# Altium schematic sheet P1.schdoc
size 297 x 210 mm; Symbol: Sheet-Symbol_A4; Company: 嘉立创EDA; Version: V1.0; Page Size: A4; @Project Name: 四轴飞行器; @Page Count: 1; @Update Date: 2025-12-14; @Create Date: 2025-11-12; @Schematic Name: Schematic1; @Page No: 1; @Page Name: P1; Device: Sheet-Symbol_A4; @Board Name: 飞行器; @Create Time: 09:09:34; @Update Time: 14:06:36
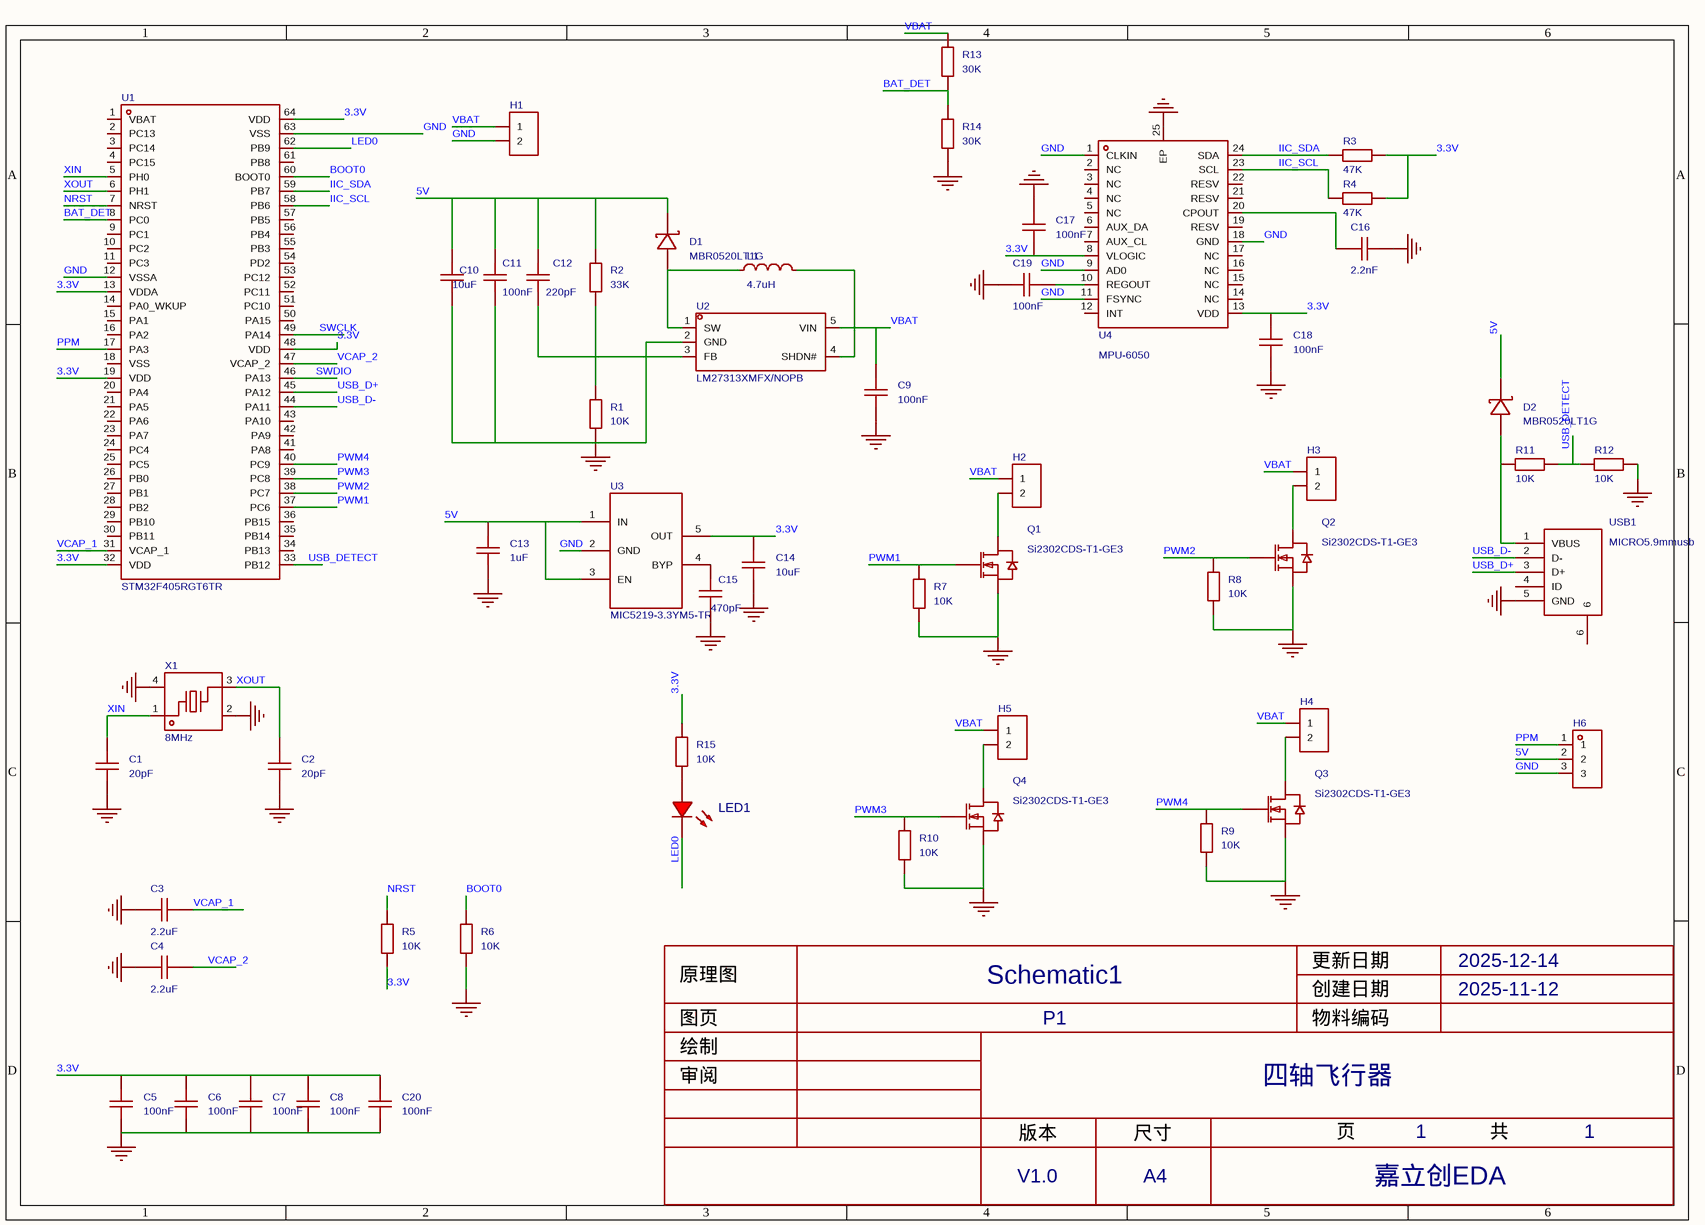
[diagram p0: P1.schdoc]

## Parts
C1  20pF  [C0603]
C2  20pF  [C0603]
C3  2.2uF  [C0603]
C4  2.2uF  [C0603]
C5  100nF  [C0603]
C6  100nF  [C0603]
C7  100nF  [C0603]
C8  100nF  [C0603]
C9  100nF  [C0603]
C10  10uF  [C0603]
C11  100nF  [C0603]
C12  220pF  [C0603]
C13  1uF  [C0603]
C14  10uF  [C0603]
C15  470pF  [C0603]
C16  2.2nF  [C0603]
C17  100nF  [C0603]
C18  100nF  [C0603]
C19  100nF  [C0603]
C20  100nF  [C0603]
D1  MBR0520LT1G  [SOD-123_L2.8-W1.8-LS3.7-RD]
D2  MBR0520LT1G  [SOD-123_L2.8-W1.8-LS3.7-RD]
H1  (no value)  [HDR-TH_2P-P2.54-V-F]
H2  (no value)  [HDR-TH_2P-P2.54-V-F]
H3  (no value)  [HDR-TH_2P-P2.54-V-F]
H4  (no value)  [HDR-TH_2P-P2.54-V-F]
H5  (no value)  [HDR-TH_2P-P2.54-V-F]
H6  (no value)  [HDR-TH_3P-P2.54-V-F]
L1  4.7uH  [IND-SMD_L5.4-W5.2_FXL0530]
LED1  (no value)  [LED_0603]
Q1  Si2302CDS-T1-GE3  [SOT-23_L2.9-W1.3-P1.90-LS2.4-BR]
Q2  Si2302CDS-T1-GE3  [SOT-23_L2.9-W1.3-P1.90-LS2.4-BR]
Q3  Si2302CDS-T1-GE3  [SOT-23_L2.9-W1.3-P1.90-LS2.4-BR]
Q4  Si2302CDS-T1-GE3  [SOT-23_L2.9-W1.3-P1.90-LS2.4-BR]
R1  10K  [R0603]
R2  33K  [R0603]
R3  47K  [R0603]
R4  47K  [R0603]
R5  10K  [R0603]
R6  10K  [R0603]
R7  10K  [R0603]
R8  10K  [R0603]
R9  10K  [R0603]
R10  10K  [R0603]
R11  10K  [R0603]
R12  10K  [R0603]
R13  30K  [R0603]
R14  30K  [R0603]
R15  10K  [R0603]
U1  STM32F405RGT6TR  [LQFP-64_L10.0-W10.0-P0.50-LS12.0-BL]
U2  LM27313XMFX/NOPB  [SOT-23-5_L3.0-W1.7-P0.95-LS2.8-BR]
U3  MIC5219-3.3YM5-TR  [SOT-23-5_L3.0-W1.7-P0.95-LS2.8-TL]
U4  MPU-6050  [QFN-24_L4.0-W4.0-P0.50-BL-EP2.7]
USB1  MICRO5.9mmusb  [MICRO-USB-SMD_5P-P0.65-H-F_MICRO5.9MMUSB]
X1  8MHz  [CRYSTAL-SMD_4P-L3.2-W2.5-BL]

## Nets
GND: C1.1 C2.1 C3.1 C4.1 C5.1 C6.1 C7.1 C8.1 C9.1 C10.1 C11.1 C13.1 C14.1 C15.1 C16.2 C17.1 C18.1 C19.1 C20.1 H1.2 H6.3 Q1.2(S) Q2.2(S) Q3.2(S) Q4.2(S) R1.1 R6.1 R7.1 R8.1 R9.1 R10.1 R12.2 R14.1 U1.12(VSSA) U1.63(VSS) U2.2(GND) U3.2(GND) U4.1(CLKIN) U4.9(AD0) U4.11(FSYNC) U4.18(GND) U4.25(EP) USB1.5(GND) X1.2(GND) X1.4(GND)
3.3V: C5.2 C6.2 C7.2 C8.2 C14.2 C17.2 C18.2 C20.2 R3.2 R4.2 R5.1 R15.2 U1.13(VDDA) U1.19(VDD) U1.32(VDD) U1.48(VDD) U1.64(VDD) U3.5(OUT) U4.8(VLOGIC) U4.13(VDD)
5V: C10.2 C11.2 C12.2 C13.2 D1.1(C) D2.1(C) H6.2 R2.2 U3.1(IN) U3.3(EN)
BAT_DET: R13.1 R14.2 U1.8(PC0)
BOOT0: R6.2 U1.60(BOOT0)
IIC_SCL: R4.1 U1.58(PB6) U4.23(SCL)
IIC_SDA: R3.1 U1.59(PB7) U4.24(SDA)
LED0: LED1.1(C) U1.62(PB9)
NRST: R5.2 U1.7(NRST)
PPM: H6.1 U1.17(PA3)
PWM1: Q1.1(G) R7.2 U1.37(PC6)
PWM2: Q2.1(G) R8.2 U1.38(PC7)
PWM3: Q4.1(G) R10.2 U1.39(PC8)
PWM4: Q3.1(G) R9.2 U1.40(PC9)
SWCLK: U1.49(PA14)
SWDIO: U1.46(PA13)
USB_D+: U1.45(PA12) USB1.3(D+)
USB_D-: U1.44(PA11) USB1.2(D-)
USB_DETECT: R11.2 R12.1 U1.33(PB12)
VBAT: C9.2 H1.1 H2.1 H3.1 H4.1 H5.1 L1.2 R13.2 U2.4(SHDN#) U2.5(VIN)
VCAP_1: C3.2 U1.31(VCAP_1)
VCAP_2: C4.2 U1.47(VCAP_2)
XIN: C1.2 U1.5(PH0) X1.1
XOUT: C2.2 U1.6(PH1) X1.3
NetC12_1: C12.1 R1.2 R2.1 U2.3(FB)
NetC15_2: C15.2 U3.4(BYP)
NetC16_1: C16.1 U4.20(CPOUT)
NetC19_2: C19.2 U4.10(REGOUT)
NetD1_2: D1.2(A) L1.1 U2.1(SW)
NetD2_2: D2.2(A) R11.1 USB1.1(VBUS)
NetH2_2: H2.2 Q1.3(D)
NetH3_2: H3.2 Q2.3(D)
NetH4_2: H4.2 Q3.3(D)
NetH5_2: H5.2 Q4.3(D)
NetLED1_2: LED1.2(A) R15.1

Not connected (* = marked no-connect by the designer): U1 1(VBAT) 2(PC13) 3(PC14) 4(PC15) 9(PC1) 10(PC2) 11(PC3) 14(PA0_WKUP) 15(PA1) 16(PA2) 18(VSS) 20(PA4) 21(PA5) 22(PA6) 23(PA7) 24(PC4) 25(PC5) 26(PB0) 27(PB1) 28(PB2) 29(PB10) 30(PB11) 34(PB13) 35(PB14) 36(PB15) 41(PA8) 42(PA9) 43(PA10) 50(PA15) 51(PC10) 52(PC11) 53(PC12) 54(PD2) 55(PB3) 56(PB4) 57(PB5) 61(PB8); U4 2(NC) 3(NC) 4(NC) 5(NC) 6(AUX_DA) 7(AUX_CL) 12(INT) 14(NC) 15(NC) 16(NC) 17(NC) 19(RESV) 21(RESV) 22(RESV); USB1 4(ID) 6

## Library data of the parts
C1-C20 = CAP_0603: ConvertToPcb: yes; SymbolName: CapAcitance; ModelId: ac125912035d415993ca9572d50418b1; ModelName: C0603_L1.6-W0.8-H0.8; ModelTransform: 62.992,31.496,0,0,0,0,0,0,0
D1 D2 = MBR0520LT1G: 正向压降(Vf):385mV@500mA;直流反向耐压(Vr):20V;整流电流:500mA;; Manufacturer: onsemi(安森美); AddInBom: yes; ModelId: 7884390a25fb4c08947731ebfba7e3f8; ModelTransform: 144.8816,62.992,0,0,0,0,0,0,0; Voltage - DC Reverse(Vr): 20V; Current - Rectified: 500mA; Reverse Leakage Current (Ir): 250uA@20V; Operating Junction Temperature Range: -65℃~+125℃; Non-Repetitive Peak Forward Surge Current: 5.5A
H1-H5 = HDR-F_2.54_1x2P: Symbol: Header-Female-2.54_1x2; ConvertToPcb: yes; ModelId: a9450ef445564560a104363b9aacde4e; ModelName: HDR-TH_2P-P2.54-F-LI-1X2P; ModelTransform: 215.7476,98.425,0,0,0,0,0,0,-129.921
H6 = HDR-F_2.54_1x3P: Symbol: PM254V-11-03-H85; ConvertToPcb: yes; ModelId: f3b3cc5aae9641bf9e56fc160cef875b; ModelName: HDR2.54-F-LI-1X3P; ModelTransform: 299.9994,100,0,0,0,0,0,0,-118.11
L1 = FXL0530-4R7-M: 电感值:4.7uH;精度:±20%;额定电流:4.5A;饱和电流(Isat):5A;类型:一体成型电感;; Manufacturer: cjiang(长江微电); AddInBom: yes; ModelId: e41ad6dce8434108a9c5d36a52ebad3b; ModelName: IND-SMD_L5.4-W5.2-H2.8_FXL0530; ModelTransform: 212.598,204.724,0,0,0,0,0,0,0; Tolerance: ±20%; Current Rating: 4.5A; Current - Saturation(Isat): 5A; DC Resistance(DCR): 60mΩ; Type: 一体成型电感
LED1 = LED_0603-R: Symbol: LED_R; Convert to PCB: yes; 3D Model: dd8257b0d61a4cd7b68939a056e08095; 3D Model Transform: 58.72,29.4,22.03,0,0,0,0,0,0; ModelName: LED-0603_R
Q1-Q4 = Si2302CDS-T1-GE3: 类型:1个N沟道;漏源电压(Vdss):20V;连续漏极电流(Id):2.9A;导通电阻(RDS(on)@Vgs,Id):57mΩ@4.5V,3.6A;功率(Pd):550mW;阈值电压(Vgs(th)@Id):850mV@250uA;; Manufacturer: VISHAY(威世); AddInBom: yes; ModelId: c62791f0466c4ae2a892c056b845b0ca; ModelName: SOT-23-3P_L2.9-W1.3-H1.0-LS2.4-P0.95; ModelTransform: 98.64468,114.173,0,180,0,0,0,0,0; Type: 1个N沟道; Drain Source Voltage (Vdss): 20V; Continuous Drain Current (Id): 2.9A; Power Dissipation (Pd): 550mW; Total Gate Charge (Qg@Vgs): 3.5nC@4.5V; Input Capacitance (Ciss@Vds): 320pF@10V; Reverse Transfer Capacitance (Crss@Vds): 5pF@10V
R1-R15 = Res_0603: Symbol: 电阻; ConvertToPcb: yes; ModelId: fc143cca1e79419f9cd78b61e9279f08; ModelTransform: 31.8897,63.7794,0,90,0,0,0,0,0
U1 = STM32F405RGT6TR: CPU内核:ARM-M4;CPU最大主频:168MHz;应用领域:-;; Manufacturer: ST(意法半导体); AddInBom: yes; ModelId: cd9de06618c44fcf82654c43a457f83c; ModelName: LQFP-64_L10.0-W10.0-H1.4-LS12.0-P0.50; ModelTransform: 472.441,472.441,0,0,0,0,0,0,0; CPU Core: ARM-M4; CPU Maximum Speed: 168MHz; Program Storage Size: 1MB; Program Memory Type: FLASH; Number of I/O: 51; ADC (Bit): 12bit; Low Voltage Detection Threshold: 1.8V~3.6V
U2 = LM27313XMFX/NOPB: 功能类型:升压型;输出类型:可调;工作电压:2.7V~14V;输出电压:5V~28V;输出电流:800mA;; Manufacturer: TI(德州仪器); AddInBom: yes; ModelId: 0a2a1b8f50944f73965918ad6e5fe167; ModelName: SOT-23-5_L2.9-W1.6-H1.1-LS2.8-P0.95; ModelTransform: 114.173,109.636,0,180,0,0,0,0,0; Function: 升压型; Output Type: 可调; Output Voltage: 5V~28V; Output Current: 800mA; Frequency - Switching: 1.6MHz; Synchronous Rectifier: 否; Number of Outputs: 1; Topology: 升压式; Switch tube (built-in/external): 内置
U3 = MIC5219-3.3YM5-TR: 输出类型:固定;最大输入电压:12V;输出电压:3.3V;输出电流:500mA;电源纹波抑制比(PSRR):75dB@(120Hz);输出极性:正极;; Manufacturer: MICROCHIP(美国微芯); AddInBom: yes; ModelId: 0a2a1b8f50944f73965918ad6e5fe167; ModelName: SOT-23-5_L2.9-W1.6-H1.1-LS2.8-P0.95; ModelTransform: 118.898,114.173,0,0,0,0,0,0,0; Output Type: 固定; Maximum Input Voltage: 12V; Output Voltage: 3.3V; Output Current: 500mA; Dropout Voltage: 600mV@(500mA); standby current: 8uA; Output Polarity: 正极; Number of Outputs: 1
U4 = MPU-6050: 传感器类型:加速度计陀螺仪;; Manufacturer: TDK InvenSense(应美盛); Symbol: MPU-6050_C24112; AddInBom: yes; ModelId: 3147e748bde04e038f0f2a42301e4816; ModelTransform: 158.267,158.267,0,0,0,0,0,0,0
USB1 = MICRO5.9mmusb: 连接器类型:Micro-B;协议标准:USB 2.0;公母:母;安装方式:卧贴;触点数量:5P;端口数量:1;额定电流 - 电源:1A;工作温度:-30℃~+80℃;; Manufacturer: SHOU HAN(首韩); AddInBom: yes; ModelId: ee791fb9720e4182be4557f9bc82cc61; ModelName: MICRO-USB-SMD_MICRO5.9MMUSB; ModelTransform: 315.054,220.472,0,180,0,0,0,-59.055,-59.055; Protocol Standard: USB 2.0; Gender: 母; Number of Contacts: 5P; Number of Ports: 1; Current Rating-Power: 1A; Detection color: 黑色
X1 = X32258MSB4SI: 晶振类型:贴片晶振;频率:8MHz;常温频差:±10ppm;负载电容:20pF;频率稳定度:±20ppm;; Manufacturer: YXC(扬兴晶振); AddInBom: yes; ModelId: 02485e56ba8d4732a26526d2983fc729; ModelTransform: 125.984,98.425,0,0,0,0,0,0,0; Normal temperature Frequency Tolerance: ±10ppm; Load Capacitance: 20pF; Frequency Stability: ±20ppm; Equivalent Series Resistance(ESR): 120Ω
